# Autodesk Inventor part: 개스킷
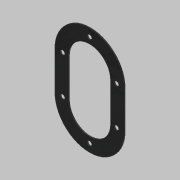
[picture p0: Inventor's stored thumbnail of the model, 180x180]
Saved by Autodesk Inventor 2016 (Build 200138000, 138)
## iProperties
Created: 2019-03
Part Number: 개스킷
Material: 고무
Document SubType Name: Modeling
Designer: mduedu
Density: 1 g/cm^3
Appearance: 고무 - 검은색 - 버전 1.1
Author: mduedu
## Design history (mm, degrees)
sketch "스케치1"
  geometry: L1 (-62, 40)-(62, 40); L2 (62, 40)-(62, -40); L3 (62, -40)-(-62, -40); L4 (-62, -40)-(-62, 40); L5 (-62, 40)-(62, -40); L6 (62, 40)-(-62, -40); 1 further point
  constraints: 12 end point, 2 midpoint, 2 parallel, 1 horizontal, 1 perpendicular
  dimensions: "d21" = 124 distance of L2.end L3.end; "d22" = 80 distance of L1.end L2.end
extrude "돌출1" new body sketch "스케치1" distance "d3" = 1; taper "d4" = 0 deg
fillet "모깎기2"
fillet "모깎기3"
sketch "스케치2" dims "d6" = 48
  geometry: L1 (-24, -22)-(24, -22); L2 (24, -22)-(24, 22); L3 (24, 22)-(-24, 22); L4 (-24, 22)-(-24, -22); L5 (-24, -22)-(24, 22); L6 (24, -22)-(-24, 22); 3 further points
  constraints: 12 end point, 4 midpoint, 2 horizontal alignment, 2 parallel, 1 horizontal, 1 perpendicular, 4 other
  dimensions: "d8" = 22 distance from line of L3 point (0, 0)
extrude "돌출2" cut sketch "스케치2" stored distance "d9" = 1; taper "d10" = 0 deg
sketch "스케치3"
  geometry: L1 (24, -22)-(24, 22) reference; L2 (-24, 22)-(-24, -22) reference; L3 (31, 22)-(31, -22); L4 (-31, -22)-(-31, 22); A1 r 24 centre (0, 22) between (24, 22) and (-24, 22) reference; A2 r 24 centre (0, -22) between (-24, -22) and (24, -22) reference; A3 r 31 centre (0, 22) between (31, 22) and (-31, 22); A4 r 31 centre (0, -22) between (-31, -22) and (31, -22); 7 further points
  constraints: 6 point on circle, 4 coincident, 4 end point, 2 centre point, 3 other
  dimensions: "d26" = 62 distance between parallel lines of L3 L4; "d28" = 7 distance between parallel lines of L4 L2 (derived); "d29" = 48 distance between parallel lines of L1 L2 (derived); "d30" = 31 radius of A3 (derived)
hole "구멍1" sketch "스케치3" at (0, 53), (31, 22), (31, -22), (0, -53), (-31, -22), (-31, 22) diameter "d14" = 5; stored, may be unused: countersink angle "d18" = 90 deg, drill point angle "d20" = 118 deg; dims "d15" = 6, "d16" = 4, "d17" = 2, "d19" = 8
node "솔리드1"
